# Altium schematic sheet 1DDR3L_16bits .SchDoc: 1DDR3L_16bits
size A3; Date: Not used; ApprovedBy: Not used; CheckedBy: Not used; Author: Not used; CompanyName: STMicroelectronics; DrawnBy: Not used; Engineer: Not used; Organization: Not used; Address1: Not used; Address2: Not used; Address3: Not used; Address4: Not used; DocumentNumber: Not used; Revision: Not used; SheetNumber: 7; SheetTotal: 7
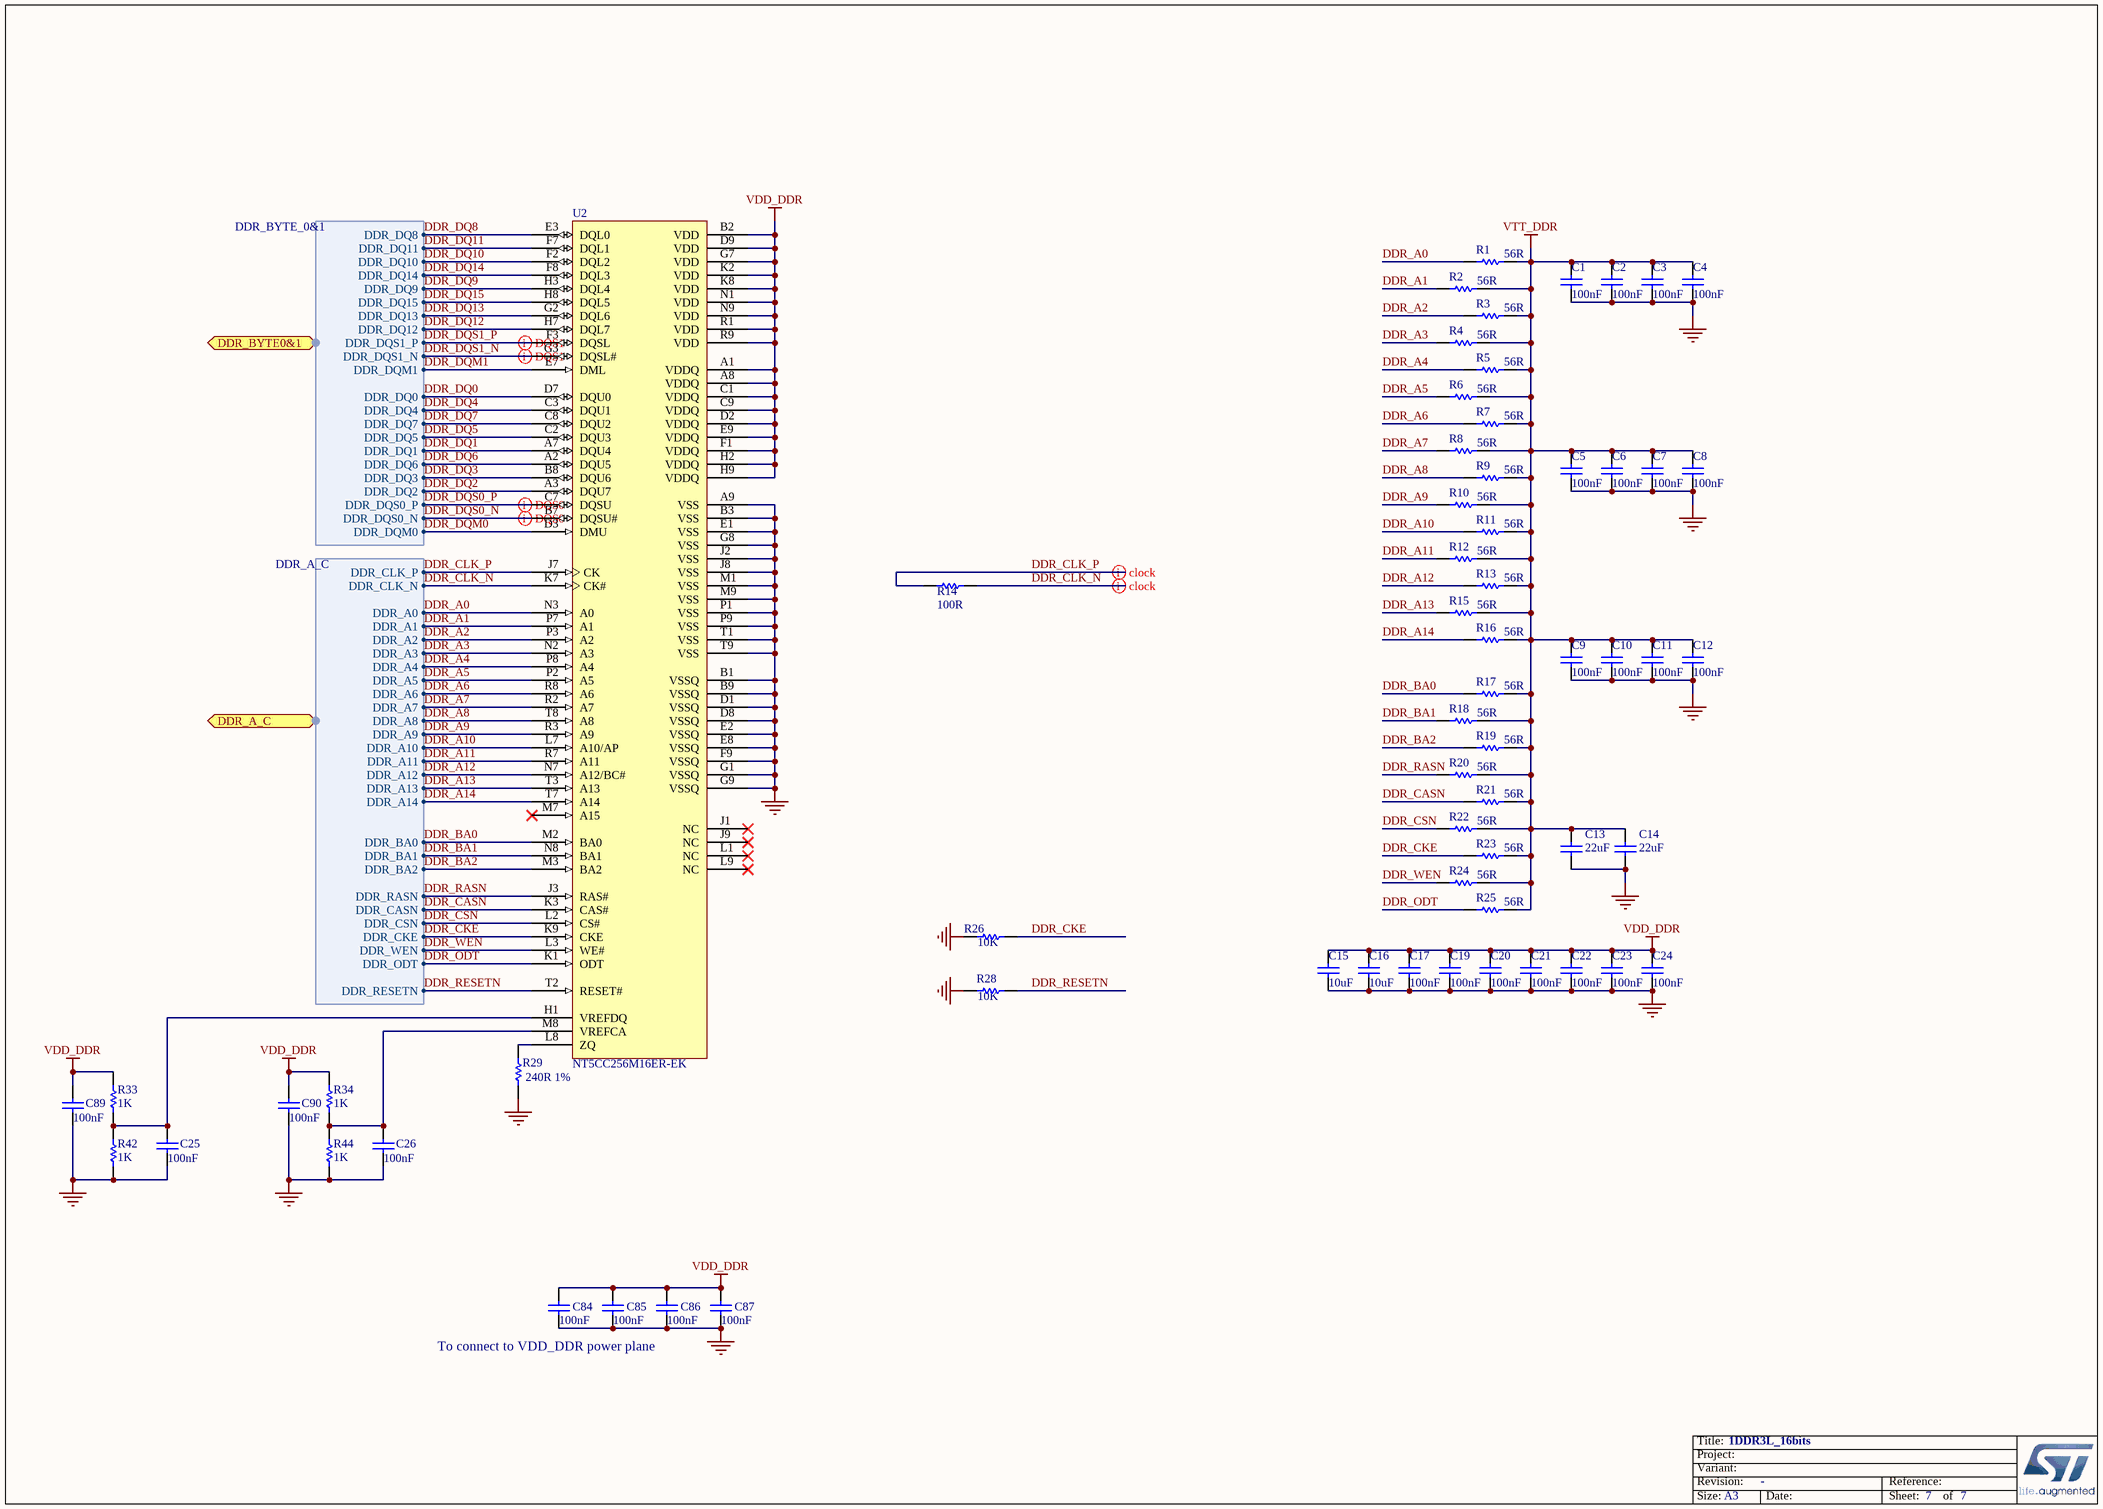
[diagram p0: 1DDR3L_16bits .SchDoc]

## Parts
C1  value 100nF  [C0402]
C2  value 100nF  [C0402]
C3  value 100nF  [C0402]
C4  value 100nF  [C0402]
C5  value 100nF  [C0402]
C6  value 100nF  [C0402]
C7  value 100nF  [C0402]
C8  value 100nF  [C0402]
C9  value 100nF  [C0402]
C10  value 100nF  [C0402]
C11  value 100nF  [C0402]
C12  value 100nF  [C0402]
C13  value 22uF  [C0603]
C14  value 22uF  [C0603]
C15  value 10uF  [C0603]
C16  value 10uF  [C0603]
C17  value 100nF  [C0402]
C19  value 100nF  [C0402]
C20  value 100nF  [C0402]
C21  value 100nF  [C0402]
C22  value 100nF  [C0402]
C23  value 100nF  [C0402]
C24  value 100nF  [C0402]
C25  value 100nF  [C0402]
C26  value 100nF  [C0402]
C84  value 100nF  [C0402]
C85  value 100nF  [C0402]
C86  value 100nF  [C0402]
C87  value 100nF  [C0402]
C89  value 100nF  [C0402]
C90  value 100nF  [C0402]
R1  value 56R  [R0402]
R2  value 56R  [R0402]
R3  value 56R  [R0402]
R4  value 56R  [R0402]
R5  value 56R  [R0402]
R6  value 56R  [R0402]
R7  value 56R  [R0402]
R8  value 56R  [R0402]
R9  value 56R  [R0402]
R10  value 56R  [R0402]
R11  value 56R  [R0402]
R12  value 56R  [R0402]
R13  value 56R  [R0402]
R14  value 100R  [R0402]
R15  value 56R  [R0402]
R16  value 56R  [R0402]
R17  value 56R  [R0402]
R18  value 56R  [R0402]
R19  value 56R  [R0402]
R20  value 56R  [R0402]
R21  value 56R  [R0402]
R22  value 56R  [R0402]
R23  value 56R  [R0402]
R24  value 56R  [R0402]
R25  value 56R  [R0402]
R26  value 10K  [R0402]
R28  value 10K  [R0402]
R29  value 240R 1%  [R0402]
R33  value 1K  [R0402]
R34  value 1K  [R0402]
R42  value 1K  [R0402]
R44  value 1K  [R0402]
U2  NT5CC256M16ER-EK  [ICC_VFBGA96_9x13_P080]

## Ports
DDR_A_C (harness DDR_A_C), DDR_BYTE0&1 (harness DDR_BYTE_0&1)

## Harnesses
DDR_A_C: DDR_A4, DDR_A0, DDR_A2, DDR_A1, DDR_A6, DDR_A3, DDR_A5, DDR_A7, DDR_A8, DDR_A9, DDR_A14, DDR_A10, DDR_A12, DDR_A11, DDR_BA0, DDR_A13, DDR_BA1, DDR_BA2, DDR_RASN, DDR_CASN, DDR_CSN, DDR_CKE, DDR_WEN, DDR_ODT, DDR_CLK_P, DDR_CLK_N, DDR_RESETN
DDR_BYTE_0&1: DDR_DQ9, DDR_DQ8, DDR_DQ10, DDR_DQ11, DDR_DQ13, DDR_DQ14, DDR_DQ15, DDR_DQ12, DDR_DQS1_P, DDR_DQS1_N, DDR_DQ7, DDR_DQM1, DDR_DQ0, DDR_DQ1, DDR_DQ4, DDR_DQ5, DDR_DQ6, DDR_DQ3, DDR_DQ2, DDR_DQS0_P, DDR_DQS0_N, DDR_DQM0

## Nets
GND: C1.2 C2.2 C3.2 C4.2 C5.2 C6.2 C7.2 C8.2 C9.2 C10.2 C11.2 C12.2 C13.1 C14.1 C15.1 C16.1 C17.2 C19.2 C20.2 C21.2 C22.2 C23.2 C24.2 C25.2 C26.2 C84.2 C85.2 C86.2 C87.2 C89.2 C90.2 R26.1 R28.1 R29.1 R42.1 R44.1 U2.A9(VSS) U2.B1(VSSQ) U2.B3(VSS) U2.B9(VSSQ) U2.D1(VSSQ) U2.D8(VSSQ) U2.E1(VSS) U2.E2(VSSQ) U2.E8(VSSQ) U2.F9(VSSQ) U2.G1(VSSQ) U2.G8(VSS) U2.G9(VSSQ) U2.J2(VSS) U2.J8(VSS) U2.M1(VSS) U2.M9(VSS) U2.P1(VSS) U2.P9(VSS) U2.T1(VSS) U2.T9(VSS)
VDD_DDR: C15.2 C16.2 C17.1 C19.1 C20.1 C21.1 C22.1 C23.1 C24.1 C84.1 C85.1 C86.1 C87.1 C89.1 C90.1 R33.2 R34.2 U2.A1(VDDQ) U2.A8(VDDQ) U2.B2(VDD) U2.C1(VDDQ) U2.C9(VDDQ) U2.D2(VDDQ) U2.D9(VDD) U2.E9(VDDQ) U2.F1(VDDQ) U2.G7(VDD) U2.H2(VDDQ) U2.H9(VDDQ) U2.K2(VDD) U2.K8(VDD) U2.N1(VDD) U2.N9(VDD) U2.R1(VDD) U2.R9(VDD)
VTT_DDR: C1.1 C2.1 C3.1 C4.1 C5.1 C6.1 C7.1 C8.1 C9.1 C10.1 C11.1 C12.1 C13.2 C14.2 R1.2 R2.2 R3.2 R4.2 R5.2 R6.2 R7.2 R8.2 R9.2 R10.2 R11.2 R12.2 R13.2 R15.2 R16.2 R17.2 R18.2 R19.2 R20.2 R21.2 R22.2 R23.2 R24.2 R25.2
DDR_A0: R1.1 U2.N3(A0) ; port DDR_A_C.DDR_A0
DDR_A1: R2.1 U2.P7(A1) ; port DDR_A_C.DDR_A1
DDR_A2: R3.1 U2.P3(A2) ; port DDR_A_C.DDR_A2
DDR_A3: R4.1 U2.N2(A3) ; port DDR_A_C.DDR_A3
DDR_A4: R5.1 U2.P8(A4) ; port DDR_A_C.DDR_A4
DDR_A5: R6.1 U2.P2(A5) ; port DDR_A_C.DDR_A5
DDR_A6: R7.1 U2.R8(A6) ; port DDR_A_C.DDR_A6
DDR_A7: R8.1 U2.R2(A7) ; port DDR_A_C.DDR_A7
DDR_A8: R9.1 U2.T8(A8) ; port DDR_A_C.DDR_A8
DDR_A9: R10.1 U2.R3(A9) ; port DDR_A_C.DDR_A9
DDR_A10: R11.1 U2.L7(A10/AP) ; port DDR_A_C.DDR_A10
DDR_A11: R12.1 U2.R7(A11) ; port DDR_A_C.DDR_A11
DDR_A12: R13.1 U2.N7(A12/BC#) ; port DDR_A_C.DDR_A12
DDR_A13: R15.1 U2.T3(A13) ; port DDR_A_C.DDR_A13
DDR_A14: R16.1 U2.T7(A14) ; port DDR_A_C.DDR_A14
DDR_BA0: R17.1 U2.M2(BA0) ; port DDR_A_C.DDR_BA0
DDR_BA1: R18.1 U2.N8(BA1) ; port DDR_A_C.DDR_BA1
DDR_BA2: R19.1 U2.M3(BA2) ; port DDR_A_C.DDR_BA2
DDR_CASN: R21.1 U2.K3(CAS#) ; port DDR_A_C.DDR_CASN
DDR_CKE: R23.1 R26.2 U2.K9(CKE) ; port DDR_A_C.DDR_CKE
DDR_CLK_N: R14.2 U2.K7(CK#) ; port DDR_A_C.DDR_CLK_N
DDR_CLK_P: R14.1 U2.J7(CK) ; port DDR_A_C.DDR_CLK_P
DDR_CSN: R22.1 U2.L2(CS#) ; port DDR_A_C.DDR_CSN
DDR_DQ0: U2.D7(DQU0) ; port DDR_BYTE0&1.DDR_DQ0
DDR_DQ1: U2.A7(DQU4) ; port DDR_BYTE0&1.DDR_DQ1
DDR_DQ2: U2.A3(DQU7) ; port DDR_BYTE0&1.DDR_DQ2
DDR_DQ3: U2.B8(DQU6) ; port DDR_BYTE0&1.DDR_DQ3
DDR_DQ4: U2.C3(DQU1) ; port DDR_BYTE0&1.DDR_DQ4
DDR_DQ5: U2.C2(DQU3) ; port DDR_BYTE0&1.DDR_DQ5
DDR_DQ6: U2.A2(DQU5) ; port DDR_BYTE0&1.DDR_DQ6
DDR_DQ7: U2.C8(DQU2) ; port DDR_BYTE0&1.DDR_DQ7
DDR_DQ8: U2.E3(DQL0) ; port DDR_BYTE0&1.DDR_DQ8
DDR_DQ9: U2.H3(DQL4) ; port DDR_BYTE0&1.DDR_DQ9
DDR_DQ10: U2.F2(DQL2) ; port DDR_BYTE0&1.DDR_DQ10
DDR_DQ11: U2.F7(DQL1) ; port DDR_BYTE0&1.DDR_DQ11
DDR_DQ12: U2.H7(DQL7) ; port DDR_BYTE0&1.DDR_DQ12
DDR_DQ13: U2.G2(DQL6) ; port DDR_BYTE0&1.DDR_DQ13
DDR_DQ14: U2.F8(DQL3) ; port DDR_BYTE0&1.DDR_DQ14
DDR_DQ15: U2.H8(DQL5) ; port DDR_BYTE0&1.DDR_DQ15
DDR_DQM0: U2.D3(DMU) ; port DDR_BYTE0&1.DDR_DQM0
DDR_DQM1: U2.E7(DML) ; port DDR_BYTE0&1.DDR_DQM1
DDR_DQS0_N: U2.B7(DQSU#) ; port DDR_BYTE0&1.DDR_DQS0_N
DDR_DQS0_P: U2.C7(DQSU) ; port DDR_BYTE0&1.DDR_DQS0_P
DDR_DQS1_N: U2.G3(DQSL#) ; port DDR_BYTE0&1.DDR_DQS1_N
DDR_DQS1_P: U2.F3(DQSL) ; port DDR_BYTE0&1.DDR_DQS1_P
DDR_ODT: R25.1 U2.K1(ODT) ; port DDR_A_C.DDR_ODT
DDR_RASN: R20.1 U2.J3(RAS#) ; port DDR_A_C.DDR_RASN
DDR_RESETN: R28.2 U2.T2(RESET#) ; port DDR_A_C.DDR_RESETN
DDR_WEN: R24.1 U2.L3(WE#) ; port DDR_A_C.DDR_WEN
NetC25_1: C25.1 R33.1 R42.2 U2.H1(VREFDQ)
NetC26_1: C26.1 R34.1 R44.2 U2.M8(VREFCA)
NetR29_2: R29.2 U2.L8(ZQ)

Not connected (* = marked no-connect by the designer): U2 J1(NC)* J9(NC)* L1(NC)* L9(NC)* M7(A15)*

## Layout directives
differential pair: DDR_CLK_N, DDR_CLK_P, DDR_DQS0_N, DDR_DQS0_P, DDR_DQS1_N, DDR_DQS1_P

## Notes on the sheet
- To connect to VDD_DDR power plane

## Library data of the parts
C1-C12 C17 C19-C26 C84-C87 C89 C90 = MCD-00006: Capacitor, MLCC, 100nF, 16V, X7R, 10%, 0402, T=0.5mm; Manufacturer_Part_Number: CC0402KRX7R7BB104; Manufacturer: YAGEO; Alternate_Manufacturer_Part_Number: GCM155R71C104KA55D; Alternate_Manufacturer: MURATA; Provided_By: SUBCO; ECCN_US: EAR99; ECCN_EU: NEC
C13 C14 = MCD-00100: Capacitor, MLCC, 22uF, 6V3, X5R, 20%, 0603, T=0,8mm; Manufacturer_Part_Number: GRM188R60J226MEA0J; Manufacturer: MURATA; Provided_By: SUBCO; ECCN_US: EAR99; ECCN_EU: NEC
C15 C16 = MCD-01124: Capacitor, MLCC, 10uF, 10V, X5R, 10%, 0603, T=0.8mm; Manufacturer_Part_Number: GRM188R61A106KAAL; Manufacturer: MURATA; Provided_By: SUBCO; ECCN_US: EAR99; ECCN_EU: NEC
R1-R13 R15-R25 = MCD-00054: Resistor,56R,0402,1%,1/16W; Manufacturer_Part_Number: RC0402FR-0756RL; Manufacturer: YAGEO; Provided_By: SUBCO; ECCN_US: EAR99; ECCN_EU: NEC
R14 = MCD-00067: Resistor,100R,0402,1%,1/16W; Manufacturer_Part_Number: RC0402FR-07100RL; Manufacturer: YAGEO; Provided_By: SUBCO; ECCN_US: EAR99; ECCN_EU: NEC
R26 R28 = MCD-00053: Resistor,10K,0402,1%,1/16W; Manufacturer_Part_Number: RC0402FR-0710KL; Manufacturer: YAGEO; Provided_By: SUBCO; ECCN_US: EAR99; ECCN_EU: NEC
R29 = MCD-00120: Resistor,240R,0402,1%,1/16W; Manufacturer_Part_Number: RC0402FR-07240RL; Manufacturer: YAGEO; Provided_By: SUBCO; ECCN_US: EAR99; ECCN_EU: NEC
R33 R34 R42 R44 = MCD-00061: Resistor,1K,0402,1%,1/16W; Manufacturer_Part_Number: RC0402FR-071KL; Manufacturer: YAGEO; Provided_By: SUBCO; ECCN_US: EAR99; ECCN_EU: NEC
U2 = MCD-01811: Memory,DDR3L,4Gb,256Mbx16,933Mhz,1V35,TFBGA; Part_Type: IC; Manufacturer: NANYA; BMS_Part_Number: 9171435; ECCN_US: tbd; Provided_By: SUBCO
